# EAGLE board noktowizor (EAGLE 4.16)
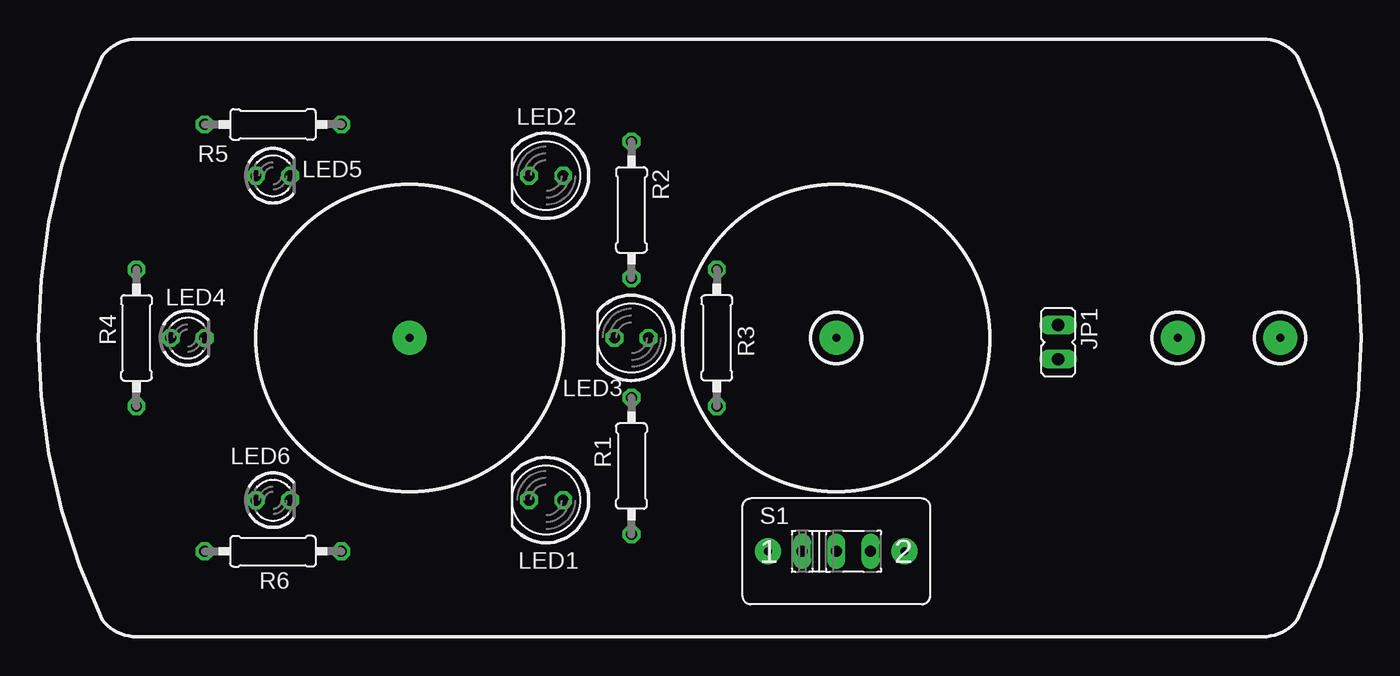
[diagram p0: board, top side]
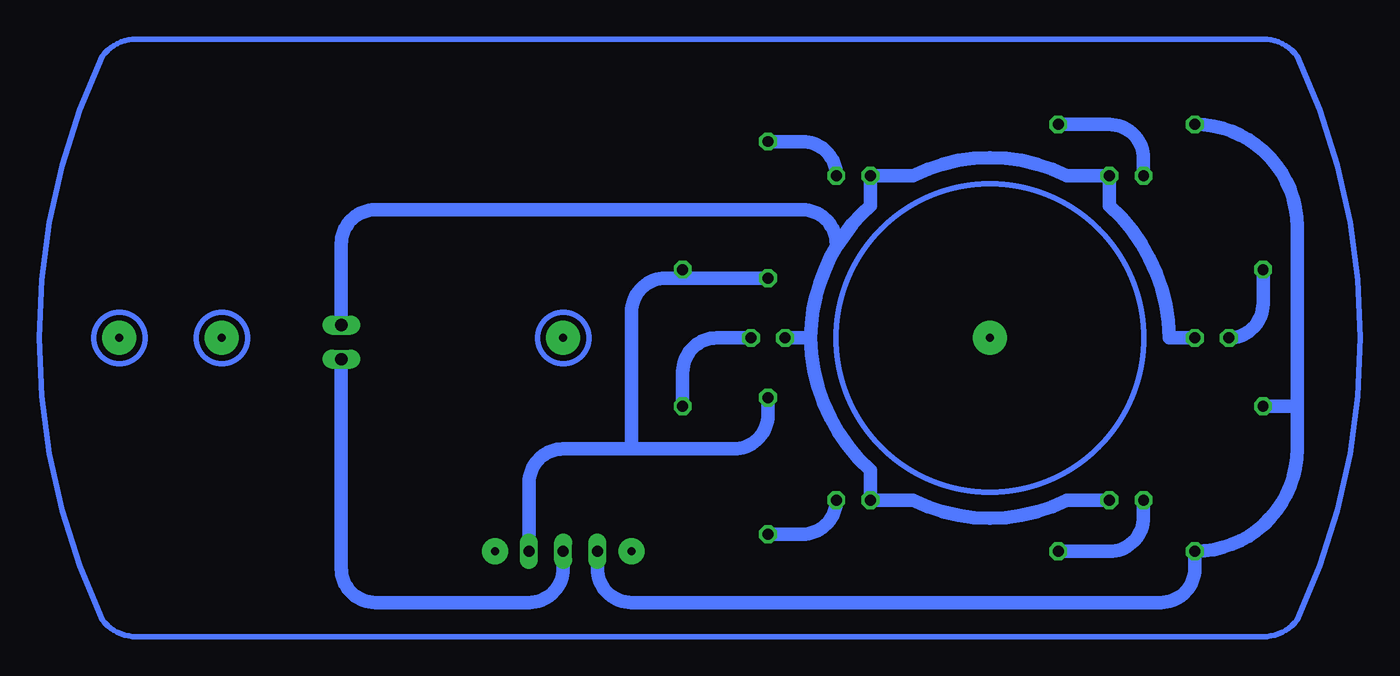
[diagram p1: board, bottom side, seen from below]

No outline drawn. Coordinates in mm, seen from the top.
Copper layers (1*16): Top 0.035mm / dielectric 1.5mm / Bottom 0.035mm
Design rules "default": minimum track width 10mil, minimum drill 24mil, track to track 8mil, track to pad 8mil, pad to pad 8mil, via to via 8mil, smd to smd 8mil, copper to edge 40mil, drill to drill 8mil, minimum pad ring 10mil, minimum via ring 8mil, stop-mask expansion 4mil, vias tented up to drill 0mil, thermal gap 10mil

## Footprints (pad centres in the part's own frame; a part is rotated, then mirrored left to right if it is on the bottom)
JP1 = drill 0.914 long: 1 0,-1.27; 2 0,1.27
LED5MM = drill 0.813 octagon: A -1.27,0; K 1.27,0
LED3MM = drill 0.813 octagon: A -1.27,0; K 1.27,0
0207/10 = drill 0.813 octagon: 1 -5.08,0; 2 5.08,0
M251 = drill 0.813 long: 1 -2.54,0; 2 0,0; 3 2.54,0

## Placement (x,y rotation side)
JP1  [JP1]  76.2,21.91 180 top
LED1  IR  [LED5MM]  38.1,10.16 180 top
LED2  IR  [LED5MM]  38.1,34.29 180 top
LED3  IR  [LED5MM]  44.45,22.23 180 top
LED4  [LED3MM]  11.43,22.23 0 top
LED5  [LED3MM]  17.78,34.29 0 top
LED6  [LED3MM]  17.78,10.16 0 top
R1  [0207/10]  44.45,12.7 90 top
R2  [0207/10]  44.45,31.75 270 top
R3  [0207/10]  50.8,22.23 90 top
R4  [0207/10]  7.62,22.23 270 top
R5  [0207/10]  17.78,38.1 180 top
R6  [0207/10]  17.78,6.35 180 top
S1  [M251]  59.69,6.35 0 top

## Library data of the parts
JP1 = jumper
LED1-LED6 = led
R1-R6 = rcl
S1 = switch

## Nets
N$6: JP1.2 S1.2
N$8: LED1.A R1.1
N$9: LED2.A R2.1
N$10: LED3.A R3.1
N$11: JP1.1 LED1.K LED2.K LED3.K LED4.K LED5.K LED6.K
N$12: LED5.A R5.1
N$13: LED6.A R6.1
N$14: R1.2 R2.2 R3.2 S1.3
N$15: R4.2 R5.2 R6.2 S1.1
N$17: LED4.A R4.1

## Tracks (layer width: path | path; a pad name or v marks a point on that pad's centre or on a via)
N$1
  Bottom 0.406: 93.98,1.27 arc-53 91.44,0 7.62,0 arc-53 5.08,1.27 arc-51 5.08,43.18 arc-53 7.62,44.45 91.44,44.45 arc-53 93.98,43.18
N$2
  Bottom 0.406: 93.98,1.27 arc51 93.98,43.18
N$3  (via drill 0.6 pad 2.54)
  other vias: 59.69,22.23
N$4  (via drill 0.6 pad 2.54)
  other vias: 85.09,22.23
N$5  (via drill 0.6 pad 2.54)
  other vias: 92.71,22.23
N$6
  Bottom 1.016: S1.2 59.69,5.08 arc90 62.23,2.54 73.66,2.54 arc90 76.2,5.08 JP1.2
N$8
  Bottom 1.016: LED1.A arc90 41.91,7.62 R1.1
N$9
  Bottom 1.016: LED2.A arc-90 41.91,36.83 R2.1
N$10
  Bottom 1.016: LED3.A 48.26,22.23 arc-90 50.8,19.68 R3.1
N$11
  Bottom 0.254: 39.28,29.15 39.37,29.21
  Bottom 1.016: 39.37,29.21 arc-90 41.91,31.75 73.66,31.75 arc-90 76.2,29.21 JP1.1 | LED6.K 22.23,10.16 arc53 33.66,10.16 LED1.K 36.83,12.38 arc47 41.27,22.23 | LED4.K 14.61,22.23 arc-47 19.05,32.07 LED5.K 22.23,34.29 arc-53 33.66,34.29 LED2.K 36.83,32.07 arc-16 39.28,29.15 arc-31 41.27,22.23 | 41.27,22.23 LED3.K
N$12
  Bottom 1.016: LED5.A 16.51,35.56 arc-90 19.05,38.1 R5.1
N$13
  Bottom 1.016: R6.1 19.05,6.35 arc-90 16.51,8.89 LED6.A
N$14
  Bottom 1.016: S1.3 62.23,11.43 arc90 59.69,13.97 54.61,13.97 | 54.61,13.97 46.99,13.97 arc-90 44.45,16.51 R1.2 | 50.8,26.67 52.07,26.67 arc-90 54.61,24.13 54.61,13.97 | 50.8,26.67 R2.2 | 50.8,26.67 R3.2
N$15
  Bottom 1.016: R5.2 arc90 5.08,30.48 5.08,17.14 | 5.08,17.14 5.08,13.97 arc90 R6.2 12.7,5.08 arc90 15.24,2.54 54.61,2.54 arc90 57.15,5.08 S1.1 | 5.08,17.14 R4.2
N$16  (via drill 0.6 pad 2.54)
  other vias: 27.94,22.23
N$17
  Bottom 1.016: LED4.A arc-90 7.62,24.77 R4.1
N$18  (via drill 0.6 pad 1.93)
  other vias: 54.61,6.35
N$19  (via drill 0.6 pad 1.93)
  other vias: 64.77,6.35
(copper drawn outside any net)
  shapes: Bottom circle x4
